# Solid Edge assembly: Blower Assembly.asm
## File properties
Author: CADCIM
Template: NORMENG.ASM
Last saved by: CADCIM
Revision: 19
Application: Solid Edge
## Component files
Lower Housing.par
upper housing.par
Blower.par
cover.par
motorshaft.par
Motor.par
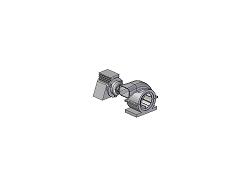
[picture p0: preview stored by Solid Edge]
